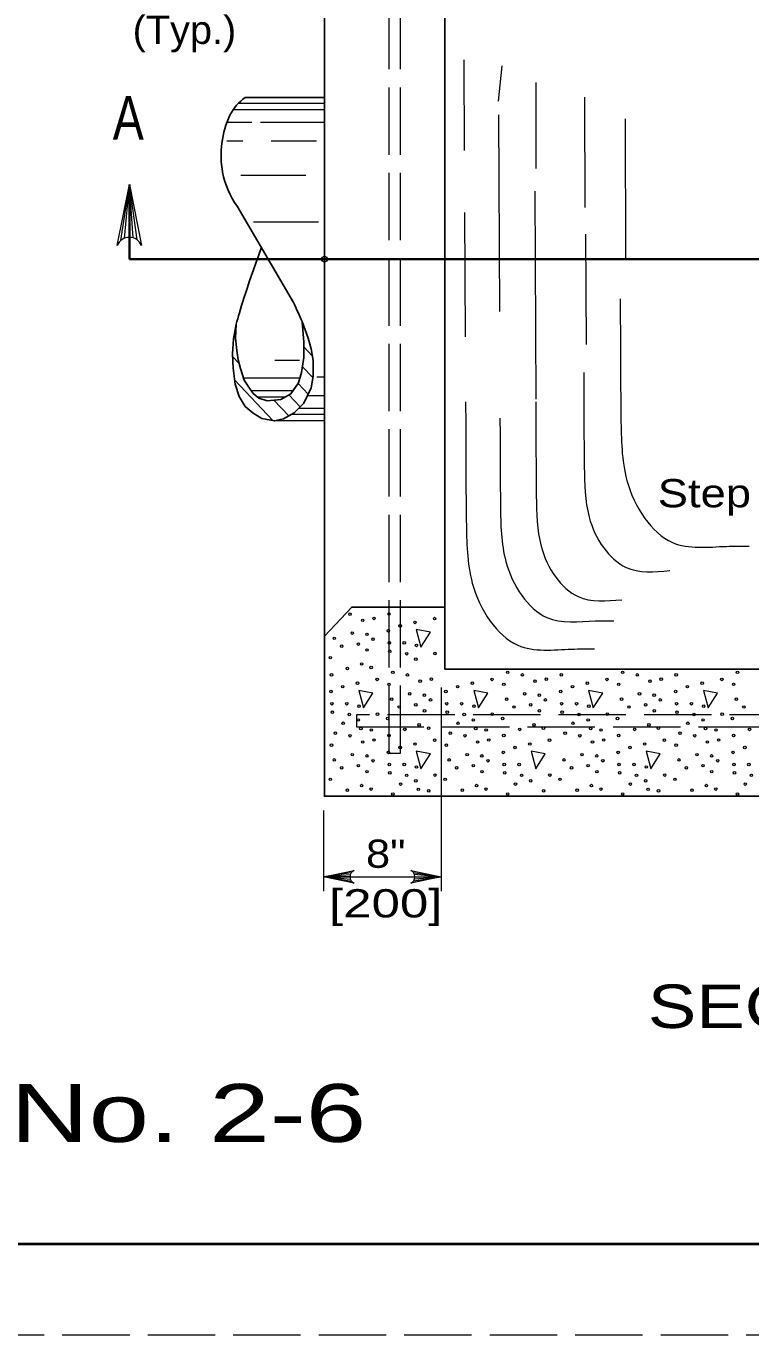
# Model space of a CAD drawing. Extents: x 1329.9 to 1363.9, y 715.5 to 737.5.
# Drawn here: x 1346.18 to 1350.19, y 715.5 to 722.72 of the extents above; entities that cross this region are included whole.
import ezdxf
from ezdxf.enums import TextEntityAlignment as Align

# ---------------------------------------------------------------- set-up
doc = ezdxf.new("R2010")
doc.units = 0
doc.header["$LTSCALE"] = 0.062
doc.header["$PDMODE"] = 32
doc.header["$PDSIZE"] = 0.031
doc.linetypes.add('LONG_DASHED', pattern=[7.5, 6, -1.5])
doc.layers.add('1', color=7, linetype='Continuous', lineweight=13)

msp = doc.modelspace()

# ---------------------------------------------------------------- linework, layer by layer
at = {"layer": '1', "linetype": 'LONG_DASHED'}
for p, q in [((1348.18833, 718.7105), (1348.18833, 724.15242)), ((1348.25092, 718.7105), (1348.25092, 724.15242)), ((1348.18833, 718.7105), (1348.25092, 718.7105))]:
    msp.add_line(p, q, dxfattribs=at)
at = {"layer": '1', "lineweight": 25}
for p, q in [((1347.83075, 719.34), (1347.83075, 723.58142)), ((1348.49467, 719.51625), (1348.49467, 723.41067)), ((1347.83075, 722.33133), (1347.39325, 722.33133)), ((1347.6595, 721.19908), (1347.34925, 721.72975)), ((1348.49467, 719.51625), (1348.49467, 719.17433))]:
    msp.add_line(p, q, dxfattribs=at)
at = {"layer": '1'}
for p, q in [((1348.60008, 722.53792), (1348.60292, 722.03808)), ((1348.79117, 722.31008), (1348.812, 722.50533)), ((1348.99933, 721.93917), (1348.99933, 722.41417)), ((1347.83075, 722.29675), (1347.35433, 722.29675)), ((1349.266, 722.3325), (1349.26933, 721.72275)), ((1347.83075, 722.26225), (1347.32625, 722.26225)), ((1348.79108, 722.23425), (1348.79692, 721.14825)), ((1349.49442, 721.4425), (1349.49308, 722.21325)), ((1347.42908, 722.193), (1347.29192, 722.193)), ((1347.83075, 722.193), (1347.47792, 722.193)), ((1347.38025, 722.08917), (1347.29192, 722.08917)), ((1347.78617, 722.08917), (1347.537, 722.08917)), ((1346.70642, 721.54117), (1346.7535, 721.84933)), ((1346.72608, 721.55283), (1346.7535, 721.84933)), ((1346.7535, 721.55817), (1346.7535, 721.84933)), ((1346.775, 721.555), (1346.7535, 721.84933)), ((1346.79608, 721.54475), (1346.7535, 721.84933)), ((1347.36992, 721.9025), (1347.72758, 721.902)), ((1348.99167, 721.81383), (1348.99783, 720.66467)), ((1348.60483, 721.69475), (1348.60858, 721.00808)), ((1347.4395, 721.64458), (1347.79717, 721.64417)), ((1349.27258, 721.57575), (1349.27592, 720.966)), ((1347.34242, 721.04967), (1347.33917, 721.05308)), ((1347.70858, 721.0885), (1347.70708, 721.08992)), ((1347.714, 721.07375), (1347.70817, 721.08008)), ((1347.34, 720.99983), (1347.33125, 721.00917)), ((1347.33983, 721.00358), (1347.33183, 721.01208)), ((1347.35892, 720.86258), (1347.32458, 720.89892)), ((1347.76367, 720.90375), (1347.71717, 720.95308)), ((1347.69308, 720.87842), (1347.55608, 720.87842)), ((1347.76625, 720.7835), (1347.70858, 720.84467)), ((1347.5465, 720.54658), (1347.3345, 720.77083)), ((1347.69525, 720.78025), (1347.3845, 720.78025)), ((1347.83075, 720.787), (1347.78883, 720.787)), ((1347.6575, 720.71117), (1347.42675, 720.71117)), ((1347.69717, 720.622), (1347.63467, 720.68808)), ((1347.741, 720.69283), (1347.68592, 720.75117)), ((1347.83075, 720.68325), (1347.73658, 720.68325)), ((1347.61467, 720.67658), (1347.4605, 720.67658)), ((1347.63325, 720.57192), (1347.55075, 720.65933)), ((1347.83075, 720.614), (1347.68908, 720.614)), ((1347.83075, 720.54475), (1347.5555, 720.54475)), ((1347.83075, 720.57933), (1347.64658, 720.57933)), ((1348.47558, 719.073), (1348.47558, 717.94792)), ((1347.82642, 718.39267), (1347.82642, 717.94792)), ((1347.97875, 718.04917), (1347.82642, 718.02667)), ((1347.97358, 718.038), (1347.82642, 718.02667)), ((1347.972, 718.02667), (1347.82642, 718.02667)), ((1347.97467, 718.01217), (1347.82642, 718.02667)), ((1347.9805, 718.00167), (1347.82642, 718.02667)), ((1347.82642, 718.02667), (1348.47558, 718.02667)), ((1348.3215, 718.05158), (1348.47558, 718.02667)), ((1348.32333, 718.00408), (1348.47558, 718.02667)), ((1348.32733, 718.04108), (1348.47558, 718.02667)), ((1348.3285, 718.01525), (1348.47558, 718.02667)), ((1348.33008, 718.02667), (1348.47558, 718.02667))]:
    msp.add_line(p, q, dxfattribs=at)
at = {"layer": '1', "lineweight": 35}
for p, q in [((1346.7535, 721.84933), (1346.7535, 721.43808)), ((1346.7535, 721.43808), (1347.83075, 721.43808)), ((1347.83075, 721.43808), (1352.11375, 721.43808))]:
    msp.add_line(p, q, dxfattribs=at)
at = {"layer": '1', "linetype": 'LONG_DASHED'}
for points in [[(1329.86333, 715.4975), (1363.86333, 715.4975), (1363.86333, 737.4975), (1329.86333, 737.4975)], [(1348.00833, 718.85575), (1353.27142, 718.85575), (1353.27142, 718.92208), (1348.00833, 718.92208)]]:
    msp.add_lwpolyline(points, close=True, dxfattribs=at)
at = {"layer": '1', "lineweight": 25}
for points in [[(1363.36333, 715.9975), (1331.86333, 715.9975), (1331.86333, 736.9975)], [(1347.70683, 721.09333), (1347.74067, 721.00183), (1347.75742, 720.94208), (1347.76808, 720.87792), (1347.76767, 720.79225), (1347.75683, 720.727), (1347.7175, 720.642), (1347.664, 720.589), (1347.60417, 720.55575), (1347.5555, 720.54475), (1347.48583, 720.55825), (1347.43775, 720.5865), (1347.39325, 720.625), (1347.35967, 720.67933), (1347.33742, 720.74767), (1347.32625, 720.8365), (1347.32392, 720.91583), (1347.32917, 720.9975), (1347.34417, 721.0795)], [(1347.70683, 721.09333), (1347.74067, 721.00183), (1347.75742, 720.94208), (1347.76808, 720.87792), (1347.76767, 720.79225), (1347.75683, 720.727), (1347.7175, 720.642), (1347.664, 720.589), (1347.60417, 720.55575), (1347.5555, 720.54475), (1347.48583, 720.55825), (1347.43775, 720.5865), (1347.39325, 720.625), (1347.35967, 720.67933), (1347.33742, 720.74767), (1347.32625, 720.8365), (1347.32392, 720.91583), (1347.32917, 720.9975), (1347.34417, 721.0795)], [(1347.34417, 721.0795), (1347.33983, 721.00217), (1347.34625, 720.9335), (1347.35383, 720.881), (1347.36658, 720.83383), (1347.38817, 720.76925), (1347.41233, 720.73017), (1347.43775, 720.69642), (1347.46842, 720.66958), (1347.51417, 720.65608), (1347.59042, 720.66283), (1347.64517, 720.69383), (1347.68833, 720.75442), (1347.70358, 720.81225), (1347.71625, 720.89442), (1347.71767, 720.97933), (1347.70683, 721.09333)], [(1347.34417, 721.0795), (1347.33983, 721.00217), (1347.34625, 720.9335), (1347.35383, 720.881), (1347.36658, 720.83383), (1347.38817, 720.76925), (1347.41233, 720.73017), (1347.43775, 720.69642), (1347.46842, 720.66958), (1347.51417, 720.65608), (1347.59042, 720.66283), (1347.64517, 720.69383), (1347.68833, 720.75442), (1347.70358, 720.81225), (1347.71625, 720.89442), (1347.71767, 720.97933), (1347.70683, 721.09333)], [(1347.83075, 719.35633), (1347.98183, 719.51625), (1348.49467, 719.51625)], [(1348.49467, 719.17433), (1352.86742, 719.17433), (1352.86742, 719.51625), (1353.34492, 719.51625), (1353.483, 719.37008)], [(1353.483, 719.36825), (1353.483, 718.47142), (1347.83075, 718.47142), (1347.83075, 719.34)]]:
    msp.add_lwpolyline(points, dxfattribs=at)
at = {"layer": '1', "lineweight": 40}
msp.add_lwpolyline([(1331.86333, 736.9975), (1363.36333, 736.9975), (1363.36333, 715.9975), (1331.86333, 715.9975)], close=True, dxfattribs=at)
msp.add_lwpolyline([(1331.86333, 736.9975), (1363.36333, 736.9975), (1363.36333, 715.9975), (1331.86333, 715.9975)], close=True, dxfattribs=at)
at = {"layer": '1'}
for points in [[(1346.68617, 721.51283), (1346.7535, 721.84933), (1346.82075, 721.51283)], [(1347.99467, 717.991), (1347.82642, 718.02667), (1347.99467, 718.06225)], [(1348.30742, 718.06225), (1348.47558, 718.02667), (1348.30742, 717.991)]]:
    msp.add_lwpolyline(points, dxfattribs=at)
for points in [[(1348.338, 719.39242), (1348.36358, 719.29508), (1348.41583, 719.37725)], [(1348.02075, 719.05658), (1348.04642, 718.95933), (1348.09867, 719.0415)], [(1348.65508, 719.05658), (1348.68075, 718.95933), (1348.733, 719.0415)], [(1349.28958, 719.05658), (1349.31525, 718.95933), (1349.36742, 719.0415)], [(1349.92392, 719.05658), (1349.94958, 718.95933), (1350.00183, 719.0415)], [(1348.338, 718.72083), (1348.36358, 718.6235), (1348.41583, 718.70567)], [(1348.97233, 718.72083), (1348.998, 718.6235), (1349.05025, 718.70567)], [(1349.60675, 718.72083), (1349.63233, 718.6235), (1349.68467, 718.70567)]]:
    msp.add_lwpolyline(points, close=True, dxfattribs=at)
msp.add_arc((1346.75356, 721.4857), 0.07261, 22.08782, 157.91395, dxfattribs=at)
at = {"layer": '1', "lineweight": 25}
for centre, major_axis, start_param, end_param in [((1347.5555, 722.08471), (0, 0.30064), 0.608535, 1.0523476), ((1347.73069, 722.01267), (0, -0.49831), 4.2528342, 4.9042115), ((1347.6858, 722.00489), (0, -0.45022), 4.9073919, 5.370128)]:
    msp.add_ellipse(centre, major_axis=major_axis, ratio=0.944544, start_param=start_param, end_param=end_param, dxfattribs=at)
at = {"layer": '1'}
for centre in [(1347.97196, 719.47764), (1348.10386, 719.45407), (1348.18697, 719.47848), (1348.43904, 719.45284), (1347.98454, 719.37308), (1348.04217, 719.44316), (1348.18385, 719.38573), (1348.24887, 719.41293), (1348.33029, 719.43196), (1347.88521, 719.34403), (1348.01795, 719.3123), (1348.06538, 719.36609), (1348.09905, 719.3395), (1348.18898, 719.31862), (1348.27124, 719.31862), (1348.33885, 719.30502), (1347.8629, 719.23702), (1347.92634, 719.30049), (1348.06622, 719.27933), (1348.19151, 719.27239), (1348.28493, 719.25879), (1348.33542, 719.22885), (1348.44078, 719.26058), (1347.95742, 719.17691), (1348.03625, 719.20226), (1348.08848, 719.18323), (1347.86977, 719.14265), (1348.01309, 719.09614), (1348.12184, 719.11702), (1348.18697, 719.08982), (1348.20838, 719.15603), (1348.28916, 719.14181), (1348.35937, 719.10734), (1348.42106, 719.11825), (1348.64749, 719.09614), (1348.75624, 719.11702), (1348.82137, 719.08982), (1348.84278, 719.15603), (1348.92356, 719.14181), (1348.99376, 719.10734), (1349.05546, 719.11825), (1349.13857, 719.14265), (1349.28189, 719.09614), (1349.39063, 719.11702), (1349.45577, 719.08982), (1349.47718, 719.15603), (1349.55796, 719.14181), (1349.62816, 719.10734), (1349.68986, 719.11825), (1349.77296, 719.14265), (1349.91629, 719.09614), (1350.02503, 719.11702), (1350.09016, 719.08982), (1350.11158, 719.15603), (1347.86665, 719.04991), (1347.93168, 719.07711), (1348.30174, 719.03726), (1348.38257, 719.03026), (1348.50105, 719.04991), (1348.56607, 719.07711), (1348.93614, 719.03726), (1349.01697, 719.03026), (1349.13545, 719.04991), (1349.20047, 719.07711), (1349.57054, 719.03726), (1349.65137, 719.03026), (1349.76985, 719.04991), (1349.83487, 719.07711), (1347.87178, 718.9828), (1347.95404, 718.9828), (1348.02165, 718.9692), (1348.20241, 719.00821), (1348.24354, 718.96467), (1348.33515, 718.97648), (1348.38342, 718.94351), (1348.41625, 719.00368), (1348.50618, 718.9828), (1348.58844, 718.9828), (1348.65605, 718.9692), (1348.8368, 719.00821), (1348.87793, 718.96467), (1348.96955, 718.97648), (1349.01782, 718.94351), (1349.05065, 719.00368), (1349.14058, 718.9828), (1349.22284, 718.9828), (1349.29045, 718.9692), (1349.4712, 719.00821), (1349.51233, 718.96467), (1349.60395, 718.97648), (1349.65222, 718.94351), (1349.68505, 719.00368), (1349.77497, 718.9828), (1349.85723, 718.9828), (1349.92485, 718.9692), (1350.1056, 719.00821), (1350.14673, 718.96467), (1347.87432, 718.93657), (1347.93427, 718.87489), (1347.96773, 718.92297), (1348.01822, 718.89302), (1348.12358, 718.92476), (1348.1801, 718.9012), (1348.50871, 718.93657), (1348.56866, 718.87489), (1348.60213, 718.92297), (1348.65262, 718.89302), (1348.75798, 718.92476), (1348.81449, 718.9012), (1349.14311, 718.93657), (1349.20306, 718.87489), (1349.23653, 718.92297), (1349.28702, 718.89302), (1349.39238, 718.92476), (1349.44889, 718.9012), (1349.77751, 718.93657), (1349.83746, 718.87489), (1349.87093, 718.92297), (1349.92141, 718.89302), (1350.02678, 718.92476), (1350.08329, 718.9012), (1347.89118, 718.82021), (1347.97196, 718.80599), (1348.03196, 718.8459), (1348.08932, 718.83767), (1348.18697, 718.80683), (1348.27462, 718.84108), (1348.35344, 718.86644), (1348.40568, 718.84741), (1348.52558, 718.82021), (1348.60636, 718.80599), (1348.66636, 718.8459), (1348.72372, 718.83767), (1348.82137, 718.80683), (1348.90902, 718.84108), (1348.98784, 718.86644), (1349.04008, 718.84741), (1349.15998, 718.82021), (1349.24076, 718.80599), (1349.30076, 718.8459), (1349.35812, 718.83767), (1349.45577, 718.80683), (1349.54342, 718.84108), (1349.62224, 718.86644), (1349.67447, 718.84741), (1349.79438, 718.82021), (1349.87516, 718.80599), (1349.93516, 718.8459), (1349.99252, 718.83767), (1350.09016, 718.80683), (1350.17782, 718.84108), (1347.86977, 718.75399), (1348.04217, 718.77151), (1348.10386, 718.78243), (1348.24887, 718.74129), (1348.33029, 718.76032), (1348.43904, 718.7812), (1348.50417, 718.75399), (1348.67657, 718.77151), (1348.73826, 718.78243), (1348.88327, 718.74129), (1348.96469, 718.76032), (1349.07343, 718.7812), (1349.31096, 718.77151), (1349.37266, 718.78243), (1349.51767, 718.74129), (1349.59909, 718.76032), (1349.70783, 718.7812), (1349.77296, 718.75399), (1349.94536, 718.77151), (1350.00706, 718.78243), (1350.15207, 718.74129), (1347.88521, 718.67239), (1347.98454, 718.70144), (1348.06538, 718.69444), (1348.09905, 718.66786), (1348.18385, 718.71409), (1348.5196, 718.67239), (1348.61894, 718.70144), (1348.69977, 718.69444), (1348.73345, 718.66786), (1348.81825, 718.71409), (1349.154, 718.67239), (1349.25334, 718.70144), (1349.33417, 718.69444), (1349.36785, 718.66786), (1349.45265, 718.71409), (1349.7884, 718.67239), (1349.88774, 718.70144), (1349.96857, 718.69444), (1350.00225, 718.66786), (1350.08705, 718.71409), (1347.92634, 718.62884), (1348.01795, 718.64065), (1348.06622, 718.60769), (1348.18898, 718.64698), (1348.19151, 718.60075), (1348.27124, 718.64698), (1348.28493, 718.58715), (1348.33885, 718.63338), (1348.44078, 718.58894), (1348.56073, 718.62884), (1348.65235, 718.64065), (1348.70062, 718.60769), (1348.82338, 718.64698), (1348.82591, 718.60075), (1348.90564, 718.64698), (1348.91933, 718.58715), (1349.07518, 718.58894), (1349.19513, 718.62884), (1349.28675, 718.64065), (1349.33502, 718.60769), (1349.45777, 718.64698), (1349.46031, 718.60075), (1349.54003, 718.64698), (1349.55373, 718.58715), (1349.60765, 718.63338), (1349.70958, 718.58894), (1349.82953, 718.62884), (1349.92115, 718.64065), (1349.96942, 718.60769), (1350.09217, 718.64698), (1350.09471, 718.60075), (1350.17443, 718.64698), (1350.18813, 718.58715), (1347.8629, 718.56537), (1348.03625, 718.53062), (1348.08848, 718.51159), (1348.25147, 718.53907), (1348.33542, 718.5572), (1348.34916, 718.51007), (1348.49729, 718.56537), (1348.67064, 718.53062), (1348.72288, 718.51159), (1348.88586, 718.53907), (1348.96982, 718.5572), (1349.13169, 718.56537), (1349.30504, 718.53062), (1349.35728, 718.51159), (1349.52026, 718.53907), (1349.60421, 718.5572), (1349.61796, 718.51007), (1349.76609, 718.56537), (1349.93944, 718.53062), (1349.99167, 718.51159), (1350.15466, 718.53907), (1347.95742, 718.50526), (1348.20838, 718.48438), (1348.40652, 718.50185), (1348.59182, 718.50526), (1348.84278, 718.48438), (1349.04092, 718.50185), (1349.22622, 718.50526), (1349.47718, 718.48438), (1349.67532, 718.50185), (1349.86062, 718.50526), (1350.11158, 718.48438)]:
    msp.add_ellipse(centre, major_axis=(0, 0.00718), ratio=0.944544, dxfattribs=at)
for centre, major_axis in [((1348.00831, 718.02663), (0, 0.03844)), ((1348.29374, 718.02663), (0, -0.03844))]:
    msp.add_ellipse(centre, major_axis=major_axis, ratio=0.944544, start_param=0.3855052, end_param=2.7561184, dxfattribs=at)
at = {"layer": '1', "lineweight": 25}
for points in [[(1347.34417, 721.0795), (1347.3615, 721.15083), (1347.39808, 721.26533), (1347.48092, 721.49817)], [(1347.6595, 721.19908), (1347.67808, 721.16017), (1347.69367, 721.125), (1347.70683, 721.09333)]]:
    msp.add_open_spline(points, degree=3, dxfattribs=at)
at = {"layer": '1'}
for points in [[(1349.46425, 721.21833), (1349.46783, 720.55967), (1349.50092, 720.21625), (1349.60025, 720.00608), (1349.75242, 719.873), (1350.05025, 719.85192), (1350.176, 719.85258)], [(1349.26267, 720.81175), (1349.26542, 720.29167), (1349.29225, 720.0135), (1349.37275, 719.84325), (1349.49608, 719.7355), (1349.73717, 719.71842)], [(1348.61042, 720.65075), (1348.614, 719.99208), (1348.64708, 719.64875), (1348.74642, 719.4385), (1348.89867, 719.30542), (1349.19642, 719.28442), (1349.32217, 719.285)], [(1348.99792, 720.65058), (1349.00067, 720.1305), (1349.0275, 719.85233), (1349.108, 719.68208), (1349.23133, 719.57433), (1349.47242, 719.55725)], [(1348.8, 720.55958), (1348.80267, 720.07692), (1348.8325, 719.76783), (1348.92183, 719.57867), (1349.05883, 719.45892), (1349.32683, 719.43992), (1349.42808, 719.44042)]]:
    msp.add_spline(points, degree=3, dxfattribs=at)
msp.add_point((1347.83075, 721.43808), dxfattribs=at)

# ---------------------------------------------------------------- texts
for s, height, width, p in [('(Typ.)', 0.156, 1.05, (1347.05762, 722.6265)), ('A', 0.24, 0.8, (1346.74758, 722.09817)), ('8"', 0.156, 1.15, (1348.16925, 718.07658)), ('[200]', 0.156, 1.35, (1348.16925, 717.8025)), ('CATCH BASINS No. 2-5 & No. 2-6', 0.32, 1.4, (1343.43337, 716.56258))]:
    msp.add_text(s, height=height, dxfattribs=dict(at, width=width)).set_placement(p, align=Align.CENTER)
for s, height, width, p in [('Step', 0.156, 1.2, (1349.67117, 720.0675)), ('SECTION C-C', 0.24, 1.25, (1349.61633, 717.192))]:
    msp.add_text(s, height=height, dxfattribs=dict(at, width=width)).set_placement(p)

doc.saveas('drawing.dxf')
